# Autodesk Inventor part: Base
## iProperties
Created: 2005-11
Part Number: Base
Document SubType Name: Modeling
Designer: Administrator
Manufacturer: Standard
Standards Organization: Custom
Author: Administrator
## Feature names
1. Extrusion1
2. Extrusion2
3. Extrusion3
4. Extrusion4
5. Extrusion5
6. Chamfer1
7. Extrusion6
8. Chamfer2
